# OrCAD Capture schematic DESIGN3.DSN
size A
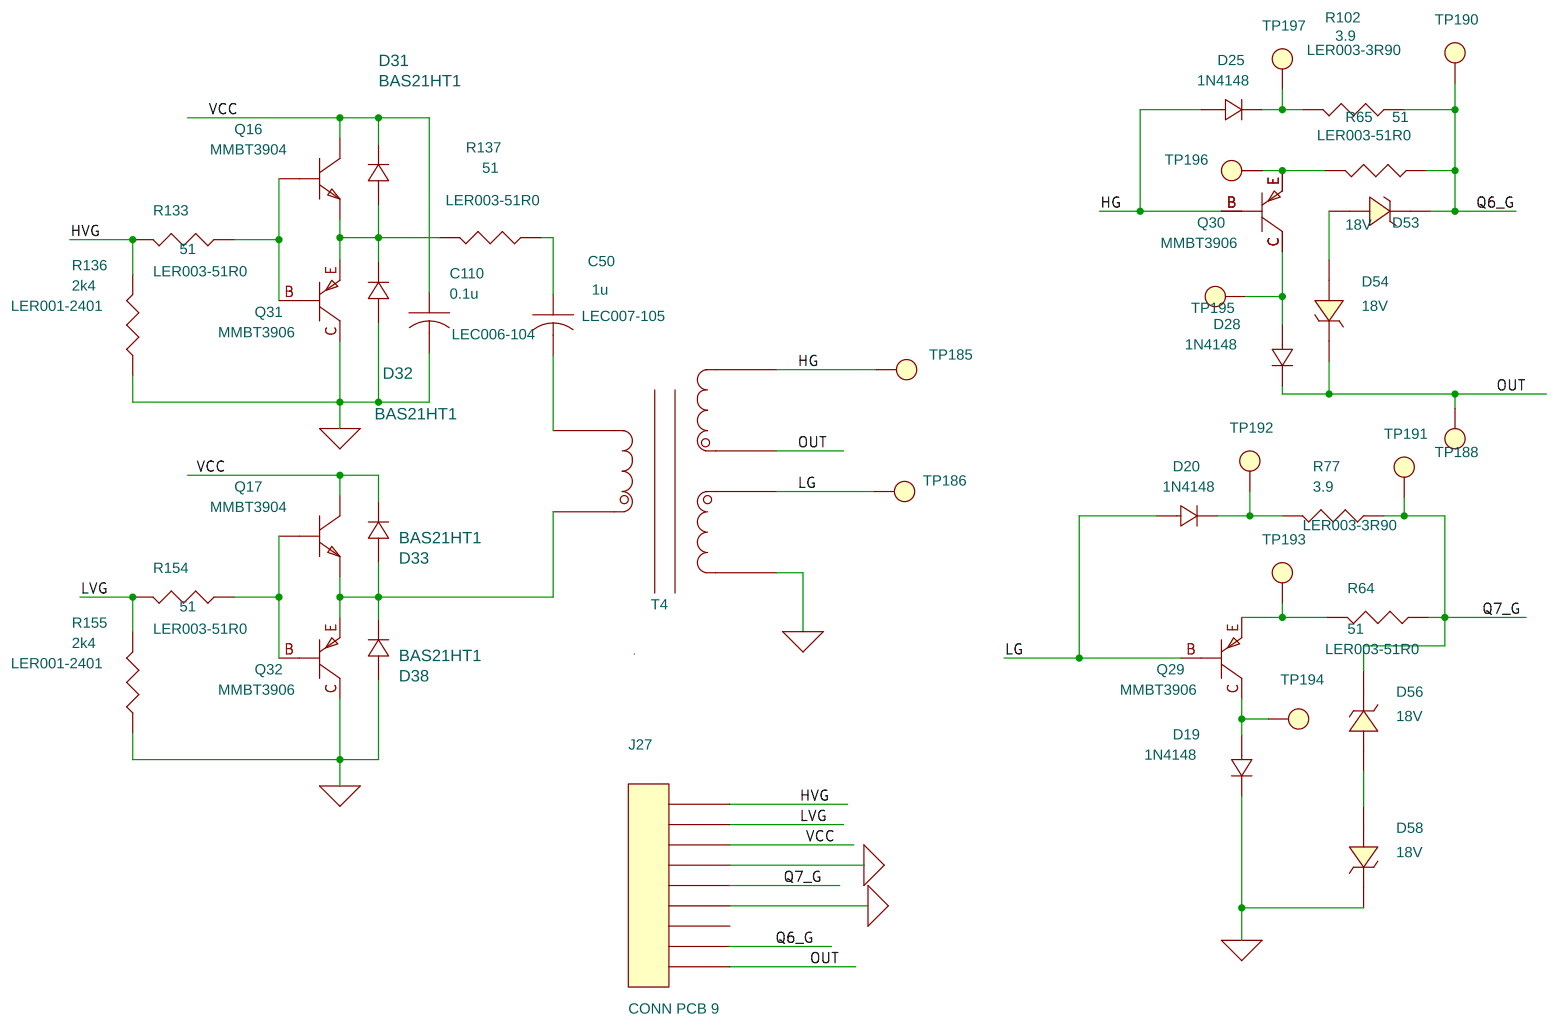
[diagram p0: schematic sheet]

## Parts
C50  1u  [c0805]
C110  0.1u  [c0603]
D19  1N4148  [SOD323]
D20  1N4148  [SOD323w]
D25  1N4148  [SOD323w]
D28  1N4148  [SOD323]
D31  BAS21HT1  [SOD323w]
D32  BAS21HT1  [SOD323w]
D33  BAS21HT1  [SOD323w]
D38  BAS21HT1  [SOD323w]
D53  18V  [SOD123]
D54  18V  [SOD123]
D56  18V  [SOD123]
D58  18V  [SOD123]
J27  CONN PCB 9  [conn9-100]
Q16  MMBT3904  [SOT23_1-32]
Q17  MMBT3904  [SOT23_1-32]
Q29  MMBT3906  [SOT23_C-BE]
Q30  MMBT3906  [SOT23_C-BE]
Q31  MMBT3906  [SOT23_C-BE]
Q32  MMBT3906  [SOT23_C-BE]
R64  51  [r0805w]
R65  51  [r0805w]
R77  3.9  [r0805w]
R102  3.9  [r0805w]
R133  51  [r0805w]
R136  2k4  [r0603]
R137  51  [r0805w]
R154  51  [r0805w]
R155  2k4  [r0603w]
T4  0.85mH  [tr_q3903_6p]
TP185  T POINT R  [tp100]
TP186  T POINT R  [tp100]
TP188  T POINT R  [tp100]
TP190  T POINT R  [tp100]
TP191  T POINT R  [tp100]
TP192  T POINT R  [tp100]
TP193  T POINT R  [tp100]
TP194  T POINT R  [tp100]
TP195  T POINT R  [tp100]
TP196  T POINT R  [tp100]
TP197  T POINT R  [tp100]

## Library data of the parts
C50 = LEC007_0805_50V: LLF Part Number: LEC007-105
C110 = LEC006_0603_50V: LLF Part Number: LEC006-104
D19 D20 D25 D28 = LED002_1N4148_SOD323
D31-D33 D38 = LED051_BAS21HT1_SOD323: LLF Part Number: LED299
D53 D54 D56 D58 = LED185_Z_7.5V_500mW_SOD123
J27 = CONN_PCB_9
Q16 Q17 = LEN006_NPN_40V_MMBT3904_SOT23
Q29-Q32 = LEN013_PNP_40V_MMBT3906_SOT23_0
R64 R65 R133 R137 R154 = LER003_0805_1: LLF Part Number: LER003-51R0
R77 R102 = LER003_0805_1: LLF Part Number: LER003-3R90
R136 R155 = LER001_0603_1: LLF Part Number: LER001-2401
T4 = T_0
TP185 TP186 TP188 TP190-TP197 = T_POINT_R

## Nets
PGND_SIGNAL: C110.2 D19.K(2) D32.A(1) D38.A(1) D58.K(CATHODE) J27.4 J27.6 Q31.C Q32.C R136.2 R155.2 T4.6
VCC: C110.1 D31.K(2) D33.K(2) J27.3 Q16.1(C) Q17.1(C)
HG: D25.A(1) Q30.B T4.1 TP185.1(TP)
HVG: J27.1 R133.1 R136.1
LG: D20.A(1) Q29.B T4.5 TP186.1(TP)
LVG: J27.2 R154.1 R155.1
OUT: D28.K(2) D54.K(CATHODE) J27.9 T4.2 TP188.1(TP)
Q6_G: D53.K(CATHODE) J27.8 R65.2 R102.2 TP190.1(TP)
Q7_G: D56.K(CATHODE) J27.5 R64.2 R77.2 TP191.1(TP)
N14075646: D31.A(1) D32.K(2) Q16.2(E) Q31.E R137.1
N14075650: Q16.3(B) Q31.B R133.2
N14075848: D33.A(1) D38.K(2) Q17.2(E) Q32.E T4.4
N14075852: Q17.3(B) Q32.B R154.2
N14076160: C50.2 T4.3
N14076164: C50.1 R137.2
N14315409: D19.A(1) Q29.C TP194.1(TP)
N14315429: D25.K(2) R102.1 TP197.1(TP)
N14315477: Q30.E R65.1 TP196.1(TP)
N14315505: D28.A(1) Q30.C TP195.1(TP)
N14315521: Q29.E R64.1 TP193.1(TP)
N14315529: D20.K(2) R77.1 TP192.1(TP)
N14315751: D53.A(ANODE) D54.A(ANODE)
N14315873: D56.A(ANODE) D58.A(ANODE)

Not connected (* = marked no-connect by the designer): J27 7
